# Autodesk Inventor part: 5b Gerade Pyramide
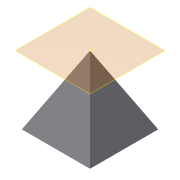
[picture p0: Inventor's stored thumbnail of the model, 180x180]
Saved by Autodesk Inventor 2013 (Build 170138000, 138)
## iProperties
Created: 2012-10
Part Number: 5b Gerade Pyramide
Material: Allgemein
Vendor: www.inventor-faq.de
Document SubType Name: Modeling
Designer: Administrator
Manufacturer: www.inventor-faq.de
Density: 1 g/cm^3
RuleStatus: InUse
AfterDocOpen0: inventorfaq
BeforeDocSave0: inventorfaq
Author: Administrator
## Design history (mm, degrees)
sketch "Skizze1"
  geometry: L1 (-5, -5)-(5, -5); L2 (5, -5)-(5, 5); L3 (5, 5)-(-5, 5); L4 (-5, 5)-(-5, -5); L5 (-5, -5)-(5, 5); L6 (5, -5)-(-5, 5); 1 further point
  constraints: 12 end point, 2 midpoint, 2 parallel, 1 horizontal, 1 perpendicular
  dimensions: "a" = 10 distance of L3.end L2.end; "d1" = 10 distance of L2.end L1.end (= a)
workpoint "Arbeitspunkt1"
  workplane "Arbeitsebene1"
feature "Erhebung auf Punkt" dims "d3" = 0, "d4" = 90 deg, "d5" = 0, "d6" = 90 deg
node "Volumenkörper1"
